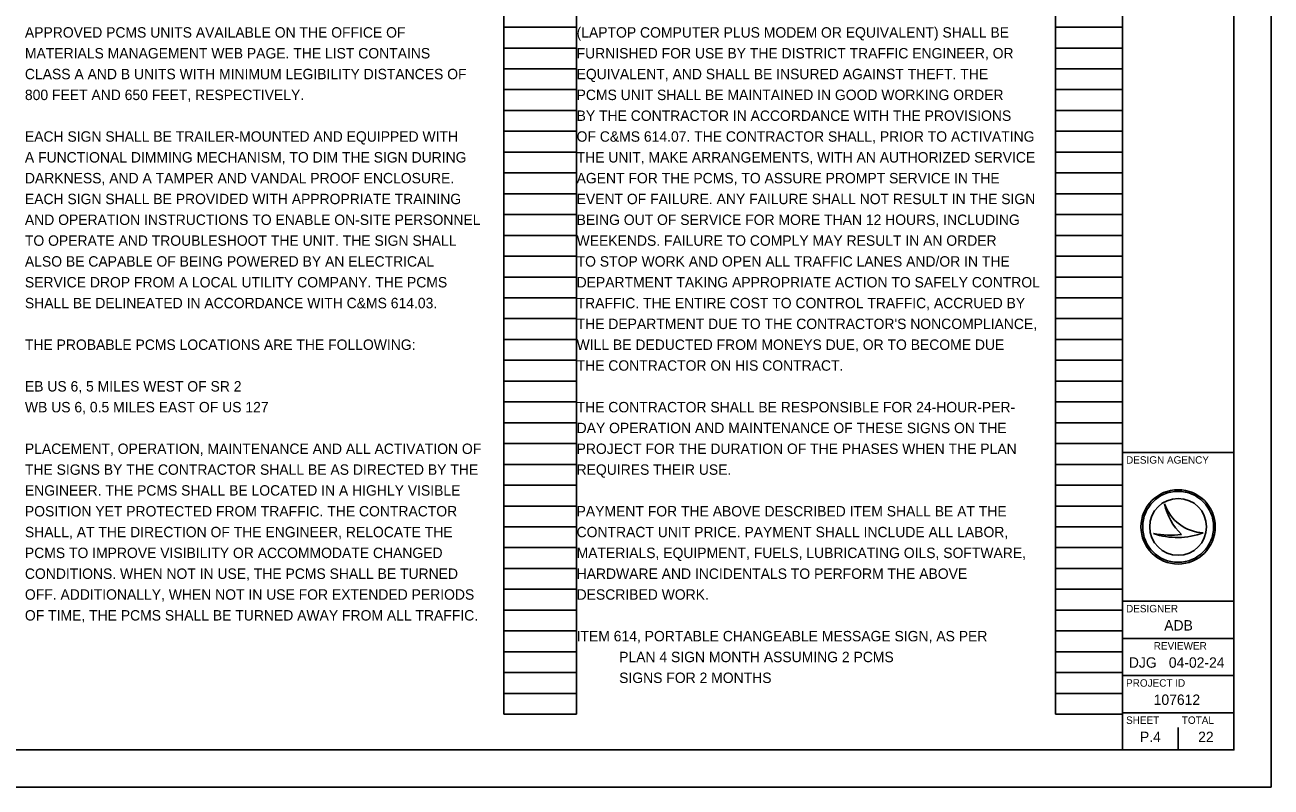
# Model space of a CAD drawing. Extents: x 0 to 34, y 0 to 22.
# Drawn here: x 17.24 to 34, y 0 to 10.25 of the extents above; entities that cross this region are included whole.
import ezdxf

# ---------------------------------------------------------------- set-up
doc = ezdxf.new("R2010")
doc.units = 0
for name, color, linetype in [('SH_Border', 7, 'Continuous'), ('SH_Cut_Line', 7, 'Continuous'), ('SH_Data', 7, 'Continuous'), ('SH_Text', 7, 'Continuous')]:
    doc.layers.add(name, color=color, linetype=linetype)

msp = doc.modelspace()

# ---------------------------------------------------------------- linework, layer by layer
at = {"layer": 'SH_Border'}
for p, q in [((32, 0.5), (32, 21.5)), ((32, 4.5), (33.5, 4.5)), ((32, 2.5), (33.5, 2.5)), ((32, 2), (33.5, 2)), ((32, 1.5), (33.5, 1.5)), ((32, 1), (33.5, 1))]:
    msp.add_line(p, q, dxfattribs=at)
msp.add_lwpolyline([(1.5, 21.5), (33.5, 21.5), (33.5, 0.5), (1.5, 0.5)], close=True, dxfattribs=at)
at = {"layer": 'SH_Cut_Line'}
msp.add_lwpolyline([(0, 0), (34, 0), (34, 22), (0, 22)], close=True, dxfattribs=at)
at = {"layer": 'SH_Data'}
for p, q in [((23.68, 0.98), (23.68, 21.14)), ((24.66, 0.98), (24.66, 21.14)), ((31.1, 0.98), (31.1, 21.14)), ((32, 0.98), (32, 21.14)), ((23.68, 10.22), (24.66, 10.22)), ((31.1, 10.22), (32, 10.22)), ((23.68, 9.94), (24.66, 9.94)), ((31.1, 9.94), (32, 9.94)), ((23.68, 9.66), (24.66, 9.66)), ((31.1, 9.66), (32, 9.66)), ((23.68, 9.38), (24.66, 9.38)), ((31.1, 9.38), (32, 9.38)), ((23.68, 9.1), (24.66, 9.1)), ((31.1, 9.1), (32, 9.1)), ((23.68, 8.82), (24.66, 8.82)), ((31.1, 8.82), (32, 8.82)), ((23.68, 8.54), (24.66, 8.54)), ((31.1, 8.54), (32, 8.54)), ((23.68, 8.26), (24.66, 8.26)), ((31.1, 8.26), (32, 8.26)), ((23.68, 7.98), (24.66, 7.98)), ((31.1, 7.98), (32, 7.98)), ((23.68, 7.7), (24.66, 7.7)), ((31.1, 7.7), (32, 7.7)), ((23.68, 7.42), (24.66, 7.42)), ((31.1, 7.42), (32, 7.42)), ((23.68, 7.14), (24.66, 7.14)), ((31.1, 7.14), (32, 7.14)), ((23.68, 6.86), (24.66, 6.86)), ((31.1, 6.86), (32, 6.86)), ((23.68, 6.58), (24.66, 6.58)), ((31.1, 6.58), (32, 6.58)), ((23.68, 6.3), (24.66, 6.3)), ((31.1, 6.3), (32, 6.3)), ((23.68, 6.02), (24.66, 6.02)), ((31.1, 6.02), (32, 6.02)), ((23.68, 5.74), (24.66, 5.74)), ((31.1, 5.74), (32, 5.74)), ((23.68, 5.46), (24.66, 5.46)), ((31.1, 5.46), (32, 5.46)), ((23.68, 5.18), (24.66, 5.18)), ((31.1, 5.18), (32, 5.18)), ((23.68, 4.9), (24.66, 4.9)), ((31.1, 4.9), (32, 4.9)), ((23.68, 4.62), (24.66, 4.62)), ((31.1, 4.62), (32, 4.62)), ((23.68, 4.34), (24.66, 4.34)), ((31.1, 4.34), (32, 4.34)), ((23.68, 4.06), (24.66, 4.06)), ((31.1, 4.06), (32, 4.06)), ((23.68, 3.78), (24.66, 3.78)), ((31.1, 3.78), (32, 3.78)), ((32.567, 3.81), (32.567, 3.81)), ((23.68, 3.5), (24.66, 3.5)), ((31.1, 3.5), (32, 3.5)), ((32.417, 3.41), (32.417, 3.41)), ((32.75, 3.5), (32.75, 3.5)), ((33.087, 3.419), (33.087, 3.419)), ((23.68, 3.22), (24.66, 3.22)), ((31.1, 3.22), (32, 3.22)), ((23.68, 2.94), (24.66, 2.94)), ((31.1, 2.94), (32, 2.94)), ((23.68, 2.66), (24.66, 2.66)), ((31.1, 2.66), (32, 2.66)), ((23.68, 2.38), (24.66, 2.38)), ((31.1, 2.38), (32, 2.38)), ((23.68, 2.1), (24.66, 2.1)), ((31.1, 2.1), (32, 2.1)), ((23.68, 1.82), (24.66, 1.82)), ((31.1, 1.82), (32, 1.82)), ((23.68, 1.54), (24.66, 1.54)), ((31.1, 1.54), (32, 1.54)), ((23.68, 1.26), (24.66, 1.26)), ((31.1, 1.26), (32, 1.26)), ((23.68, 0.98), (24.66, 0.98)), ((31.1, 0.98), (32, 0.98)), ((32.375, 0.675), (32.375, 0.675)), ((32.75, 0.5), (32.75, 0.8))]:
    msp.add_line(p, q, dxfattribs=at)
for radius in [0.5, 0.477, 0.477, 0.382]:
    msp.add_circle((32.75, 3.5), radius, dxfattribs=at)
for centre, radius, start, end in [((33.116, 3.998), 0.58, 198.9257, 198.9319), ((33.347, 3.97), 0.796, 191.6379, 191.6421), ((33.116, 3.998), 0.58, 198.9319, 267.1657), ((33.347, 3.97), 0.796, 191.6421, 226.0947), ((32.739, 4.37), 1.013, 251.4576, 290.0832), ((32.648, 4.654), 1.266, 259.4964, 259.4995), ((32.739, 4.37), 1.013, 251.4527, 251.4576), ((32.648, 4.654), 1.266, 259.4995, 276.6672)]:
    msp.add_arc(centre, radius, start, end, dxfattribs=at)

# ---------------------------------------------------------------- texts
for s, height, p in [('DESIGN AGENCY', 0.1, (32.05, 4.35)), ('DESIGNER', 0.1, (32.05, 2.35)), ('ADB', 0.14, (32.563, 2.105)), ('REVIEWER', 0.1, (32.422, 1.85)), ('DJG', 0.14, (32.087, 1.605)), ('04-02-24', 0.14, (32.625, 1.605)), ('PROJECT ID', 0.1, (32.05, 1.35)), ('107612', 0.14, (32.421, 1.105)), ('SHEET', 0.1, (32.05, 0.85)), ('TOTAL', 0.1, (32.8, 0.85)), ('P.4', 0.14, (32.237, 0.605)), ('22', 0.14, (33.019, 0.605))]:
    msp.add_text(s, height=height, dxfattribs=at).set_placement(p)
at = {"layer": 'SH_Text'}
for s, p in [('(LAPTOP COMPUTER PLUS MODEM OR EQUIVALENT) SHALL BE', (24.66, 10.08)), ('APPROVED PCMS UNITS AVAILABLE ON THE OFFICE OF', (17.24, 10.08)), ('MATERIALS MANAGEMENT WEB PAGE. THE LIST CONTAINS', (17.24, 9.8)), ('FURNISHED FOR USE BY THE DISTRICT TRAFFIC ENGINEER, OR', (24.66, 9.8)), ('CLASS A AND B UNITS WITH MINIMUM LEGIBILITY DISTANCES OF', (17.24, 9.52)), ('EQUIVALENT, AND SHALL BE INSURED AGAINST THEFT. THE', (24.66, 9.52)), ('800 FEET AND 650 FEET, RESPECTIVELY.', (17.24, 9.24)), ('PCMS UNIT SHALL BE MAINTAINED IN GOOD WORKING ORDER', (24.66, 9.24)), ('BY THE CONTRACTOR IN ACCORDANCE WITH THE PROVISIONS', (24.66, 8.96)), ('EACH SIGN SHALL BE TRAILER-MOUNTED AND EQUIPPED WITH', (17.24, 8.68)), ('OF C&MS 614.07. THE CONTRACTOR SHALL, PRIOR TO ACTIVATING', (24.66, 8.68)), ('A FUNCTIONAL DIMMING MECHANISM, TO DIM THE SIGN DURING', (17.24, 8.4)), ('THE UNIT, MAKE ARRANGEMENTS, WITH AN AUTHORIZED SERVICE', (24.66, 8.4)), ('DARKNESS, AND A TAMPER AND VANDAL PROOF ENCLOSURE.', (17.24, 8.12)), ('AGENT FOR THE PCMS, TO ASSURE PROMPT SERVICE IN THE', (24.66, 8.12)), ('EACH SIGN SHALL BE PROVIDED WITH APPROPRIATE TRAINING', (17.24, 7.84)), ('EVENT OF FAILURE. ANY FAILURE SHALL NOT RESULT IN THE SIGN', (24.66, 7.84)), ('AND OPERATION INSTRUCTIONS TO ENABLE ON-SITE PERSONNEL', (17.24, 7.56)), ('BEING OUT OF SERVICE FOR MORE THAN 12 HOURS, INCLUDING', (24.66, 7.56)), ('TO OPERATE AND TROUBLESHOOT THE UNIT. THE SIGN SHALL', (17.24, 7.28)), ('WEEKENDS. FAILURE TO COMPLY MAY RESULT IN AN ORDER', (24.66, 7.28)), ('ALSO BE CAPABLE OF BEING POWERED BY AN ELECTRICAL', (17.24, 7)), ('TO STOP WORK AND OPEN ALL TRAFFIC LANES AND/OR IN THE', (24.66, 7)), ('SERVICE DROP FROM A LOCAL UTILITY COMPANY. THE PCMS', (17.24, 6.72)), ('DEPARTMENT TAKING APPROPRIATE ACTION TO SAFELY CONTROL', (24.66, 6.72)), ('SHALL BE DELINEATED IN ACCORDANCE WITH C&MS 614.03.', (17.24, 6.44)), ('TRAFFIC. THE ENTIRE COST TO CONTROL TRAFFIC, ACCRUED BY', (24.66, 6.44)), ("THE DEPARTMENT DUE TO THE CONTRACTOR'S NONCOMPLIANCE,", (24.66, 6.16)), ('THE PROBABLE PCMS LOCATIONS ARE THE FOLLOWING:', (17.24, 5.88)), ('WILL BE DEDUCTED FROM MONEYS DUE, OR TO BECOME DUE', (24.66, 5.88)), ('THE CONTRACTOR ON HIS CONTRACT.', (24.66, 5.6)), ('EB US 6, 5 MILES WEST OF SR 2', (17.24, 5.32)), ('WB US 6, 0.5 MILES EAST OF US 127', (17.24, 5.04)), ('THE CONTRACTOR SHALL BE RESPONSIBLE FOR 24-HOUR-PER-', (24.66, 5.04)), ('DAY OPERATION AND MAINTENANCE OF THESE SIGNS ON THE', (24.66, 4.76)), ('PLACEMENT, OPERATION, MAINTENANCE AND ALL ACTIVATION OF', (17.24, 4.48)), ('PROJECT FOR THE DURATION OF THE PHASES WHEN THE PLAN', (24.66, 4.48)), ('THE SIGNS BY THE CONTRACTOR SHALL BE AS DIRECTED BY THE', (17.24, 4.2)), ('REQUIRES THEIR USE.', (24.66, 4.2)), ('ENGINEER. THE PCMS SHALL BE LOCATED IN A HIGHLY VISIBLE', (17.24, 3.92)), ('POSITION YET PROTECTED FROM TRAFFIC. THE CONTRACTOR', (17.24, 3.64)), ('PAYMENT FOR THE ABOVE DESCRIBED ITEM SHALL BE AT THE', (24.66, 3.64)), ('SHALL, AT THE DIRECTION OF THE ENGINEER, RELOCATE THE', (17.24, 3.36)), ('CONTRACT UNIT PRICE. PAYMENT SHALL INCLUDE ALL LABOR,', (24.66, 3.36)), ('PCMS TO IMPROVE VISIBILITY OR ACCOMMODATE CHANGED', (17.24, 3.08)), ('MATERIALS, EQUIPMENT, FUELS, LUBRICATING OILS, SOFTWARE,', (24.66, 3.08)), ('CONDITIONS. WHEN NOT IN USE, THE PCMS SHALL BE TURNED', (17.24, 2.8)), ('HARDWARE AND INCIDENTALS TO PERFORM THE ABOVE', (24.66, 2.8)), ('OFF. ADDITIONALLY, WHEN NOT IN USE FOR EXTENDED PERIODS', (17.24, 2.52)), ('DESCRIBED WORK.', (24.66, 2.52)), ('OF TIME, THE PCMS SHALL BE TURNED AWAY FROM ALL TRAFFIC.', (17.24, 2.24)), ('ITEM 614, PORTABLE CHANGEABLE MESSAGE SIGN, AS PER', (24.66, 1.96)), ('           PLAN 4 SIGN MONTH ASSUMING 2 PCMS', (24.66, 1.68)), ('           SIGNS FOR 2 MONTHS', (24.66, 1.4))]:
    msp.add_text(s, height=0.14, dxfattribs=at).set_placement(p)

doc.saveas('drawing.dxf')
